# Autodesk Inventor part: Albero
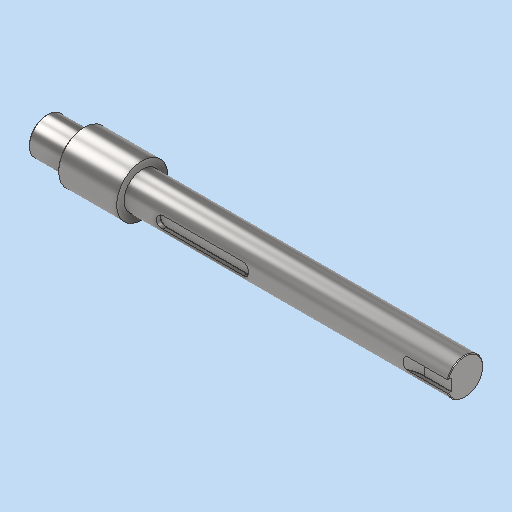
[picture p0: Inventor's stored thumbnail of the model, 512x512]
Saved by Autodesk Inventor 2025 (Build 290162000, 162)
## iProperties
CustomPartVersion: 1
Created: 2026-05
Part Number: Albero
Material: Steel
Document SubType Name: Modeling
Designer: R5800u
Density: 1 g/cm^3
Appearance: Semilucidato
Length: 285,000 mm
Author: R5800u
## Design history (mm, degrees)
sketch "Schizzo principale"
  geometry: L1 (0, 0)-(285, 0) reference; L2 (0, 0)-(0, 12.5); L3 (0, 12.5)-(25, 12.5); L4 (25, 12.5)-(25, 17.5); L5 (65, 17.5)-(65, 12.5); L6 (25, 17.5)-(65, 17.5); L7 (285, 12.5)-(285, 0); L8 (65, 12.5)-(285, 12.5)
  constraints: 16 end point, 4 vertical, 3 horizontal
  dimensions: "d3" = 25 diameter of L3 L1 (derived); "d4" = 35 diameter of L6 L1 (derived); "d5" = 25 diameter of L8 L1 (derived)
revolve "Rivoluzione1" sketch "Schizzo principale" stored, may be unused: angle "d6" = 0 deg
chamfer "Smusso4" distance "d17" = 0.5; stored, may be unused: second distance "d18" = 0.125, angle "d19" = 45 deg
chamfer "Smusso3" distance "d14" = 0.5; stored, may be unused: second distance "d15" = 0.125, angle "d16" = 45 deg
chamfer "Smusso1" distance "d7" = 0.5; stored, may be unused: second distance "d8" = 0.125, angle "d9" = 45 deg
node "Scanalatura1"
node "Scanalatura2"
node "Solido1"
feature "Sede per chiavetta albero"
feature "Sede per chiavetta albero2"
other parameters: "d0" = 0, "d1" = 0, "d2" = 0, "Length" = 285 [user parameter]
